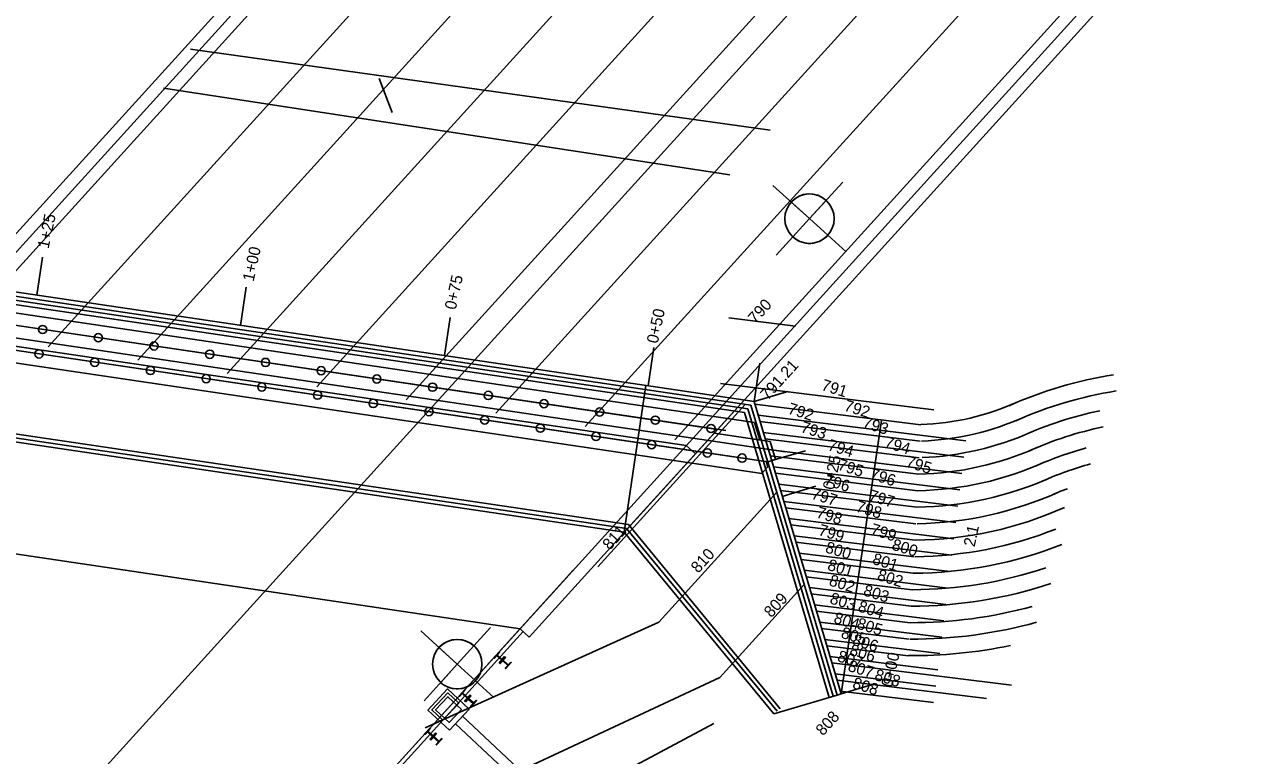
# Model space of a CAD drawing. Extents: x 1465887 to 1476191, y 569684 to 581027.
# Drawn here: x 1469566.9 to 1469715.4, y 574017.1 to 574105.8 of the extents above; entities that cross this region are included whole.
import ezdxf

# ---------------------------------------------------------------- set-up
doc = ezdxf.new("R2010")
doc.units = 0
for name, color, linetype in [('BR_P_Beam_Centerline', 7, 'Continuous'), ('BR_P_Brg_Centerline', 7, 'Continuous'), ('BR_P_Gen_Approach_Slab', 7, 'Continuous'), ('BR_P_Gen_Ground_Slope', 7, 'Continuous'), ('BR_P_Gen_Perforated_Pipe', 7, 'Continuous'), ('BR_P_Gen_Porous_Backfill', 7, 'Continuous'), ('BR_P_Gen_Profile_Grade', 7, 'Continuous'), ('BR_P_Gen_Slope_Protection', 7, 'Continuous'), ('BR_P_Rail_Object', 7, 'Continuous'), ('BR_P_Sub_Deep_Centerline', 7, 'Continuous'), ('BR_P_Sub_Deep_Hidden', 7, 'Continuous'), ('BR_P_Sub_Foot_Hidden', 7, 'Continuous'), ('BR_P_Sub_Hidden', 7, 'Continuous'), ('BR_P_Sub_Object', 7, 'Continuous'), ('DR_P_Cells', 7, 'Continuous'), ('DR_P_Paved_Gutter', 7, 'Continuous'), ('DR_P_Storm_Sewer', 7, 'Continuous'), ('GK_Drainage_Nodes', 7, 'Continuous'), ('GT_Project_Soil_Boring', 7, 'Continuous'), ('PV_X_EOP', 7, 'Continuous'), ('PV_X_Shoulder', 7, 'Continuous'), ('RD_P_Anchor_Assembly', 7, 'Continuous'), ('SC_Scratch1', 7, 'Continuous')]:
    doc.layers.add(name, color=color, linetype=linetype)

msp = doc.modelspace()

# ---------------------------------------------------------------- linework, layer by layer
at = {"layer": 'BR_P_Beam_Centerline'}
for p, q in [((1469558.94, 574068.28), (1469670.01, 574190.58)), ((1469569.81, 574066.67), (1469680.87, 574188.97)), ((1469580.67, 574065.06), (1469691.74, 574187.37)), ((1469591.54, 574063.45), (1469702.6, 574185.76)), ((1469602.4, 574061.85), (1469713.47, 574184.15)), ((1469613.27, 574060.24), (1469724.33, 574182.54)), ((1469624.13, 574058.63), (1469735.2, 574180.93)), ((1469635, 574057.02), (1469746.07, 574179.32)), ((1469645.86, 574055.41), (1469756.93, 574177.71))]:
    msp.add_line(p, q, dxfattribs=at)
at = {"layer": 'BR_P_Brg_Centerline'}
msp.add_line((1469545.48, 574070.78), (1469659.26, 574053.94), dxfattribs=at)
at = {"layer": 'BR_P_Gen_Approach_Slab'}
for p, q in [((1469556.75, 574068.1), (1469647.25, 574054.7)), ((1469536.58, 574045.89), (1469627.08, 574032.49))]:
    msp.add_line(p, q, dxfattribs=at)
at = {"layer": 'BR_P_Gen_Ground_Slope'}
for p, q in [((1469652.4, 574070.19), (1469660.52, 574069.19)), ((1469651.42, 574062.25), (1469677.32, 574059.06)), ((1469654.39, 574059.71), (1469636.5, 574040.02)), ((1469655.58, 574059.72), (1469675.73, 574057.24)), ((1469655.98, 574058.4), (1469681.19, 574055.3)), ((1469656.2, 574057.63), (1469675.64, 574055.24)), ((1469656.6, 574056.31), (1469680.95, 574053.31)), ((1469656.83, 574055.54), (1469675.54, 574053.24)), ((1469657.22, 574054.22), (1469680.7, 574051.33)), ((1469657.45, 574053.45), (1469675.45, 574051.23)), ((1469657.84, 574052.13), (1469680.46, 574049.34)), ((1469658.07, 574051.36), (1469675.35, 574049.23)), ((1469658.23, 574049.07), (1469643.91, 574033.3)), ((1469658.47, 574050.04), (1469680.21, 574047.36)), ((1469658.7, 574049.26), (1469675.24, 574047.23)), ((1469659.09, 574047.94), (1469679.97, 574045.37)), ((1469659.32, 574047.17), (1469675.13, 574045.23)), ((1469659.71, 574045.85), (1469679.73, 574043.39)), ((1469659.94, 574045.08), (1469675.02, 574043.22)), ((1469660.33, 574043.76), (1469679.48, 574041.4)), ((1469660.56, 574042.99), (1469674.91, 574041.22)), ((1469638.15, 574042.46), (1469638.17, 574042.44)), ((1469660.96, 574041.67), (1469679.24, 574039.42)), ((1469661.19, 574040.9), (1469674.79, 574039.22)), ((1469661.58, 574039.58), (1469678.99, 574037.43)), ((1469661.81, 574038.81), (1469674.67, 574037.22)), ((1469661.57, 574037.87), (1469651.31, 574026.57)), ((1469662.2, 574037.48), (1469678.75, 574035.45)), ((1469662.43, 574036.71), (1469674.55, 574035.22)), ((1469662.83, 574035.39), (1469678.5, 574033.46)), ((1469663.06, 574034.62), (1469674.43, 574033.22)), ((1469643.91, 574033.3), (1469615.56, 574020.46)), ((1469663.45, 574033.3), (1469678.26, 574031.48)), ((1469663.68, 574032.53), (1469674.3, 574031.22)), ((1469664.07, 574031.21), (1469678.02, 574029.49)), ((1469664.3, 574030.44), (1469674.17, 574029.22)), ((1469664.69, 574029.12), (1469677.77, 574027.51)), ((1469664.92, 574028.35), (1469686.72, 574025.66)), ((1469651.31, 574026.57), (1469602.16, 574003.67)), ((1469665.32, 574027.03), (1469677.53, 574025.52)), ((1469665.55, 574026.25), (1469683.68, 574024.02)), ((1469665.94, 574024.93), (1469677.28, 574023.54)), ((1469650.58, 574021.02), (1469608.08, 573998.29))]:
    msp.add_line(p, q, dxfattribs=at)
for centre, radius, start, end in [((1469706.87, 574013.91), 50, 98.9137, 114.1221), ((1469706.87, 574013.91), 48, 98.9137, 114.1221), ((1469674.57, 574088.7), 31.47, 272.109, 294.1274), ((1469674.57, 574088.7), 33.47, 272.109, 294.1274), ((1469706.87, 574013.91), 46, 101.7999, 114.1221), ((1469674.57, 574088.7), 35.47, 272.109, 294.1274), ((1469706.87, 574013.91), 44, 101.7999, 114.1221), ((1469674.57, 574088.7), 37.47, 271.3449, 294.1274), ((1469706.87, 574013.91), 42, 105.2856, 114.1221), ((1469674.57, 574088.7), 39.47, 271.1298, 294.1274), ((1469706.87, 574013.91), 40, 105.2856, 114.1221), ((1469674.57, 574088.7), 41.47, 270.9306, 294.1274), ((1469674.57, 574088.7), 43.47, 270.9306, 294.1274), ((1469706.87, 574013.91), 38, 110.5883, 114.1221), ((1469674.57, 574088.7), 45.47, 270.5723, 294.1274), ((1469674.57, 574088.7), 47.47, 270.5723, 291.6687), ((1469674.57, 574088.7), 49.47, 270.2585, 291.6687), ((1469674.57, 574088.7), 51.47, 270.1155, 288.473), ((1469674.57, 574088.7), 53.47, 269.9806, 288.473), ((1469674.57, 574088.7), 55.47, 269.8531, 285.3443), ((1469674.57, 574088.7), 57.47, 269.8531, 285.3443), ((1469674.57, 574088.7), 59.47, 269.6177, 281.6574)]:
    msp.add_arc(centre, radius, start, end, dxfattribs=at)
at = {"layer": 'BR_P_Gen_Perforated_Pipe'}
for p, q in [((1469559.15, 574073.31), (1469654.71, 574059.16)), ((1469559.21, 574072.79), (1469654.32, 574058.71)), ((1469545.56, 574059.14), (1469640.25, 574045.12)), ((1469654.71, 574059.16), (1469665.08, 574024.31)), ((1469545.61, 574058.63), (1469639.99, 574044.66)), ((1469654.32, 574058.71), (1469664.6, 574024.16)), ((1469639.99, 574044.66), (1469658.28, 574022.49)), ((1469640.25, 574045.12), (1469658.67, 574022.8))]:
    msp.add_line(p, q, dxfattribs=at)
at = {"layer": 'BR_P_Gen_Porous_Backfill'}
for p, q in [((1469545.66, 574058.12), (1469639.73, 574044.19)), ((1469639.73, 574044.19), (1469657.89, 574022.17)), ((1469657.89, 574022.17), (1469665.56, 574024.45))]:
    msp.add_line(p, q, dxfattribs=at)
at = {"layer": 'BR_P_Gen_Profile_Grade'}
msp.add_line((1469397.14, 573817.97), (1469976.08, 574455.48), dxfattribs=at)
at = {"layer": 'BR_P_Gen_Slope_Protection'}
for p, q in [((1469559.03, 574074.33), (1469655.48, 574060.05)), ((1469559.09, 574073.82), (1469655.1, 574059.61)), ((1469655.1, 574059.61), (1469665.56, 574024.45)), ((1469655.48, 574060.05), (1469666.04, 574024.59)), ((1469666.04, 574024.59), (1469665.56, 574024.45))]:
    msp.add_line(p, q, dxfattribs=at)
at = {"layer": 'BR_P_Rail_Object'}
for p, q in [((1469535.47, 574046.9), (1469687.68, 574214.51)), ((1469627.08, 574032.49), (1469779.29, 574200.1)), ((1469628.19, 574031.49), (1469780.4, 574199.09)), ((1469536.58, 574045.89), (1469612.41, 574129.39)), ((1469647.25, 574054.7), (1469648.36, 574053.69)), ((1469627.08, 574032.49), (1469628.19, 574031.49))]:
    msp.add_line(p, q, dxfattribs=at)
at = {"layer": 'BR_P_Sub_Deep_Centerline'}
for p, q in [((1469554.55, 574070.95), (1469652.07, 574056.52)), ((1469549.14, 574068.72), (1469655.26, 574053.01))]:
    msp.add_line(p, q, dxfattribs=at)
at = {"layer": 'BR_P_Sub_Deep_Hidden'}
for centre in [(1469569.14, 574068.79), (1469575.9, 574067.79), (1469582.66, 574066.79), (1469568.7, 574065.83), (1469575.46, 574064.82), (1469589.42, 574065.79), (1469596.18, 574064.79), (1469596.18, 574064.79), (1469582.22, 574063.82), (1469602.94, 574063.79), (1469588.98, 574062.82), (1469595.74, 574061.82), (1469595.74, 574061.82), (1469609.7, 574062.79), (1469616.46, 574061.79), (1469602.5, 574060.82), (1469623.22, 574060.79), (1469609.26, 574059.82), (1469616.02, 574058.82), (1469629.98, 574059.79), (1469636.74, 574058.79), (1469622.78, 574057.82), (1469643.5, 574057.79), (1469629.54, 574056.82), (1469636.3, 574055.82), (1469650.26, 574056.78), (1469643.06, 574054.82), (1469649.82, 574053.82), (1469654.03, 574053.19)]:
    msp.add_circle(centre, 0.5, dxfattribs=at)
at = {"layer": 'BR_P_Sub_Foot_Hidden'}
for p, q in [((1469555.7, 574072.3), (1469655.54, 574057.52)), ((1469547.12, 574067.51), (1469656.44, 574051.32)), ((1469655.54, 574057.52), (1469656.17, 574055.4)), ((1469656.44, 574051.32), (1469657.15, 574052.13)), ((1469656.96, 574052.76), (1469657.15, 574052.13))]:
    msp.add_line(p, q, dxfattribs=at)
at = {"layer": 'BR_P_Sub_Hidden'}
for p, q in [((1469556.99, 574070.59), (1469651.06, 574056.67)), ((1469554.56, 574067.92), (1469648.63, 574053.99)), ((1469651.06, 574056.67), (1469650.65, 574056.22))]:
    msp.add_line(p, q, dxfattribs=at)
at = {"layer": 'BR_P_Sub_Object'}
for p, q in [((1469650.65, 574056.22), (1469657.45, 574055.22)), ((1469657.45, 574055.22), (1469658.1, 574053.02)), ((1469648.63, 574053.99), (1469657.14, 574052.73)), ((1469657.14, 574052.73), (1469658.1, 574053.02))]:
    msp.add_line(p, q, dxfattribs=at)
at = {"layer": 'DR_P_Cells'}
for points in [[(1469618.5, 574020.19), (1469620.9, 574022.74), (1469618.29, 574025.19), (1469615.89, 574022.64)], [(1469617.7, 574021.4), (1469619.64, 574023.47), (1469618.3, 574024.72), (1469616.36, 574022.66)], [(1469619.96, 574022.71), (1469618.47, 574021.13), (1469616.83, 574022.67), (1469618.32, 574024.25)]]:
    msp.add_lwpolyline(points, close=True, dxfattribs=at)
at = {"layer": 'DR_P_Paved_Gutter'}
for p, q in [((1469627.08, 574032.49), (1469609.6, 574013.25)), ((1469627.45, 574032.16), (1469609.97, 574012.91))]:
    msp.add_line(p, q, dxfattribs=at)
at = {"layer": 'DR_P_Storm_Sewer'}
for p, q in [((1469619.25, 574020.98), (1469632.25, 574008.77)), ((1469620.11, 574021.89), (1469633.11, 574009.68))]:
    msp.add_line(p, q, dxfattribs=at)
at = {"layer": 'GK_Drainage_Nodes'}
for p, q in [((1469617.09, 574023.92), (1469617.09, 574023.92)), ((1469617.58, 574023.46), (1469617.58, 574023.46)), ((1469619.14, 574023.48), (1469619.14, 574023.48)), ((1469618.4, 574022.69), (1469618.4, 574022.69)), ((1469618.4, 574022.69), (1469618.4, 574022.69)), ((1469618.4, 574022.69), (1469618.4, 574022.69)), ((1469618.67, 574022.43), (1469618.67, 574022.43)), ((1469618.67, 574022.43), (1469618.67, 574022.43)), ((1469617.65, 574021.9), (1469617.65, 574021.9)), ((1469619.22, 574021.92), (1469619.22, 574021.92)), ((1469619.7, 574021.47), (1469619.7, 574021.47))]:
    msp.add_line(p, q, dxfattribs=at)
at = {"layer": 'GT_Project_Soil_Boring'}
for p, q in [((1469662.21, 574082.23), (1469657.77, 574086.26)), ((1469662.21, 574082.23), (1469666.25, 574086.67)), ((1469664.23, 574084.45), (1469662.21, 574082.23)), ((1469662.21, 574082.23), (1469659.99, 574084.25)), ((1469662.21, 574082.23), (1469658.18, 574077.79)), ((1469660.2, 574080.01), (1469662.21, 574082.23)), ((1469662.21, 574082.23), (1469666.65, 574078.2)), ((1469662.21, 574082.23), (1469664.43, 574080.21)), ((1469619.46, 574028.2), (1469623.5, 574032.64)), ((1469619.46, 574028.2), (1469615.02, 574032.23)), ((1469619.46, 574028.2), (1469617.24, 574030.22)), ((1469621.48, 574030.42), (1469619.46, 574028.2)), ((1469619.46, 574028.2), (1469615.43, 574023.76)), ((1469617.45, 574025.98), (1469619.46, 574028.2)), ((1469619.46, 574028.2), (1469623.91, 574024.17)), ((1469619.46, 574028.2), (1469621.69, 574026.18))]:
    msp.add_line(p, q, dxfattribs=at)
for centre in [(1469662.21, 574082.23), (1469619.46, 574028.2)]:
    msp.add_circle(centre, 3, dxfattribs=at)
for centre, start, end in [((1469662.21, 574082.23), 47.7565, 137.7565), ((1469662.21, 574082.23), 227.7565, 317.7565), ((1469619.46, 574028.2), 47.7565, 137.7565), ((1469619.46, 574028.2), 227.7565, 317.7565)]:
    msp.add_arc(centre, 3, start, end, dxfattribs=at)
at = {"layer": 'PV_X_EOP'}
msp.add_line((1469587.06, 574102.79), (1469657.45, 574092.95), dxfattribs=at)
at = {"layer": 'PV_X_Shoulder'}
msp.add_line((1469583.81, 574098.06), (1469652.53, 574087.53), dxfattribs=at)
at = {"layer": 'RD_P_Anchor_Assembly'}
for p, q in [((1469628.42, 574033.98), (1469633.53, 574039.6)), ((1469628.42, 574033.98), (1469611.62, 574015.47)), ((1469624.58, 574029.68), (1469623.92, 574028.95)), ((1469624.95, 574028.69), (1469624.22, 574029.35)), ((1469624.85, 574028.71), (1469624.26, 574029.26)), ((1469624.91, 574028.78), (1469624.32, 574029.32)), ((1469625.25, 574029.08), (1469624.59, 574028.35)), ((1469625.31, 574029.02), (1469624.65, 574028.29)), ((1469625.68, 574028.02), (1469624.95, 574028.69)), ((1469625.58, 574028.05), (1469624.99, 574028.59)), ((1469625.64, 574028.12), (1469625.05, 574028.66)), ((1469625.98, 574028.42), (1469625.31, 574027.69)), ((1469620.38, 574025.06), (1469619.72, 574024.33)), ((1469620.75, 574024.06), (1469620.02, 574024.72)), ((1469620.65, 574024.09), (1469620.06, 574024.63)), ((1469620.71, 574024.15), (1469620.11, 574024.69)), ((1469621.05, 574024.45), (1469620.38, 574023.73)), ((1469621.11, 574024.39), (1469620.45, 574023.67)), ((1469621.48, 574023.4), (1469620.75, 574024.06)), ((1469621.38, 574023.42), (1469620.78, 574023.97)), ((1469621.44, 574023.49), (1469620.84, 574024.03)), ((1469621.77, 574023.79), (1469621.11, 574023.06)), ((1469616.18, 574020.43), (1469615.52, 574019.7)), ((1469616.55, 574019.43), (1469615.82, 574020.09)), ((1469616.45, 574019.46), (1469615.85, 574020)), ((1469616.51, 574019.53), (1469615.91, 574020.07)), ((1469616.84, 574019.83), (1469616.18, 574019.1)), ((1469616.91, 574019.77), (1469616.25, 574019.04)), ((1469617.27, 574018.77), (1469616.55, 574019.43)), ((1469617.18, 574018.8), (1469616.58, 574019.34)), ((1469617.24, 574018.86), (1469616.64, 574019.41)), ((1469617.57, 574019.17), (1469616.91, 574018.44))]:
    msp.add_line(p, q, dxfattribs=at)
for points in [[(1469624.62, 574029.65), (1469623.96, 574028.92), (1469623.89, 574028.98), (1469624.55, 574029.71)], [(1469624.91, 574028.78), (1469624.85, 574028.71), (1469624.26, 574029.26), (1469624.32, 574029.32)], [(1469625.21, 574029.11), (1469624.55, 574028.38), (1469624.62, 574028.32), (1469625.28, 574029.05)], [(1469625.35, 574028.99), (1469624.68, 574028.26), (1469624.62, 574028.32), (1469625.28, 574029.05)], [(1469625.64, 574028.12), (1469625.58, 574028.05), (1469624.99, 574028.59), (1469625.05, 574028.66)], [(1469625.94, 574028.45), (1469625.28, 574027.72), (1469625.35, 574027.66), (1469626.01, 574028.39)], [(1469620.42, 574025.03), (1469619.75, 574024.3), (1469619.69, 574024.36), (1469620.35, 574025.09)], [(1469620.71, 574024.15), (1469620.65, 574024.09), (1469620.06, 574024.63), (1469620.11, 574024.69)], [(1469621.01, 574024.48), (1469620.35, 574023.75), (1469620.42, 574023.7), (1469621.08, 574024.42)], [(1469621.14, 574024.36), (1469620.48, 574023.64), (1469620.42, 574023.7), (1469621.08, 574024.42)], [(1469621.44, 574023.49), (1469621.38, 574023.42), (1469620.78, 574023.97), (1469620.84, 574024.03)], [(1469621.74, 574023.82), (1469621.08, 574023.09), (1469621.15, 574023.03), (1469621.81, 574023.76)], [(1469616.21, 574020.4), (1469615.55, 574019.67), (1469615.49, 574019.73), (1469616.15, 574020.46)], [(1469616.51, 574019.53), (1469616.45, 574019.46), (1469615.85, 574020), (1469615.91, 574020.07)], [(1469616.81, 574019.86), (1469616.15, 574019.13), (1469616.22, 574019.07), (1469616.88, 574019.8)], [(1469616.94, 574019.74), (1469616.28, 574019.01), (1469616.22, 574019.07), (1469616.88, 574019.8)], [(1469617.24, 574018.86), (1469617.18, 574018.8), (1469616.58, 574019.34), (1469616.64, 574019.41)], [(1469617.54, 574019.2), (1469616.88, 574018.47), (1469616.94, 574018.41), (1469617.61, 574019.14)]]:
    msp.add_lwpolyline(points, close=True, dxfattribs=at)
at = {"layer": 'SC_Scratch1'}
for p, q in [((1469609.96, 574099.21), (1469611.57, 574095.11)), ((1469569.12, 574077.57), (1469568.43, 574072.94)), ((1469593.85, 574073.91), (1469593.16, 574069.28)), ((1469618.58, 574070.25), (1469617.89, 574065.62)), ((1469643.31, 574066.59), (1469642.62, 574061.96)), ((1469656.17, 574064.69), (1469655.48, 574060.05)), ((1469639.73, 574044.19), (1469642.36, 574062)), ((1469659.57, 574061.27), (1469655.48, 574060.05)), ((1469654.29, 574060.23), (1469639.73, 574044.19)), ((1469666.04, 574024.59), (1469670.95, 574057.76)), ((1469661.71, 574054.09), (1469657.62, 574052.88)), ((1469662.99, 574049.77), (1469658.91, 574048.55)), ((1469670.13, 574025.81), (1469666.04, 574024.59))]:
    msp.add_line(p, q, dxfattribs=at)

# ---------------------------------------------------------------- texts
at = {"layer": 'BR_P_Gen_Ground_Slope'}
for s, rotation, p in [('790', 47.7564, (1469655.64, 574069.4)), ('791.21', 47.7564, (1469657.13, 574060.12)), ('791', 342.7564, (1469663.55, 574061.47)), ('792', 342.7564, (1469659.48, 574058.61)), ('792', 342.7564, (1469666.31, 574058.97)), ('793', 342.7564, (1469661.04, 574056.37)), ('793', 342.7564, (1469668.56, 574056.93)), ('794', 342.7564, (1469664.33, 574054.19)), ('794', 342.7564, (1469671.2, 574054.53)), ('795', 342.7564, (1469665.54, 574051.81)), ('795', 342.7564, (1469673.8, 574052.17)), ('796', 342.7564, (1469669.43, 574050.68)), ('796', 342.7564, (1469663.89, 574049.99)), ('797', 342.7564, (1469662.33, 574048.28)), ('797', 342.7564, (1469669.29, 574048.08)), ('798', 342.7564, (1469662.94, 574046.02)), ('798', 342.7564, (1469667.74, 574046.75)), ('811', 47.7564, (1469637.97, 574041.94)), ('799', 342.7564, (1469663.19, 574043.89)), ('799', 342.7564, (1469669.52, 574043.98)), ('2:1', 77.9025, (1469682.25, 574042.36)), ('800', 342.7564, (1469664.03, 574041.79)), ('800', 342.7564, (1469672.1, 574042.12)), ('810', 47.7564, (1469648.7, 574039.15)), ('801', 342.7564, (1469669.74, 574040.39)), ('801', 342.7564, (1469664.29, 574039.66)), ('802', 342.7564, (1469664.48, 574037.78)), ('802', 342.7564, (1469670.33, 574038.43)), ('809', 47.7564, (1469657.57, 574033.76)), ('803', 342.7564, (1469664.58, 574035.6)), ('803', 342.7564, (1469668.64, 574036.57)), ('804', 342.7564, (1469667.99, 574034.63)), ('804', 342.7564, (1469665.05, 574033.24)), ('805', 342.7564, (1469667.84, 574032.55)), ('805', 342.7564, (1469665.93, 574031.43)), ('806', 342.7564, (1469667.31, 574030.58)), ('807', 342.7564, (1469665.5, 574028.59)), ('806', 342.7564, (1469666.97, 574029.34)), ('807', 342.7564, (1469666.77, 574027.41)), ('808', 342.7564, (1469667.33, 574025.32)), ('808', 342.7564, (1469670, 574026.32)), ('808', 47.6493, (1469663.85, 574019.43))]:
    msp.add_text(s, height=1.4, rotation=rotation, dxfattribs=at).set_placement(p)
at = {"layer": 'SC_Scratch1'}
for s, p in [('1+25', (1469569.85, 574078.52)), ('1+00', (1469594.74, 574074.54)), ('0+75', (1469619.27, 574071.11)), ('0+50', (1469643.79, 574067.02)), ('0+25', (1469665.16, 574049.26)), ('0+00', (1469672.26, 574025.34))]:
    msp.add_text(s, height=1.4, rotation=77.7564, dxfattribs=at).set_placement(p)

doc.saveas('drawing.dxf')
